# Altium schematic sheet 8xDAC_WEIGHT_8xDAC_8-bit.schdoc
size 420 x 297 mm; Symbol: Drawing-Symbol_A4; @Project Name: Inverted_MAML_6x6; @Page Count: 1; @Update Date: 2026-06-15; @Create Date: 2026-06-15; @Schematic Name: Schematic1; @Page No: 1; @Page Name: P1; Company: EasyEDA.com; Version: V1.0; Page Size: A4; Drawn: Olle Welin; Device: Drawing-Symbol_A4; @Create Time: 21:23:07; @Update Time: 21:23:07; Border: 1; Width: 1655; Height: 1170; Region Start: 1; X Region Count: 6; Y Region Count: 4; Blade Width: 10; Title Block Position: 3
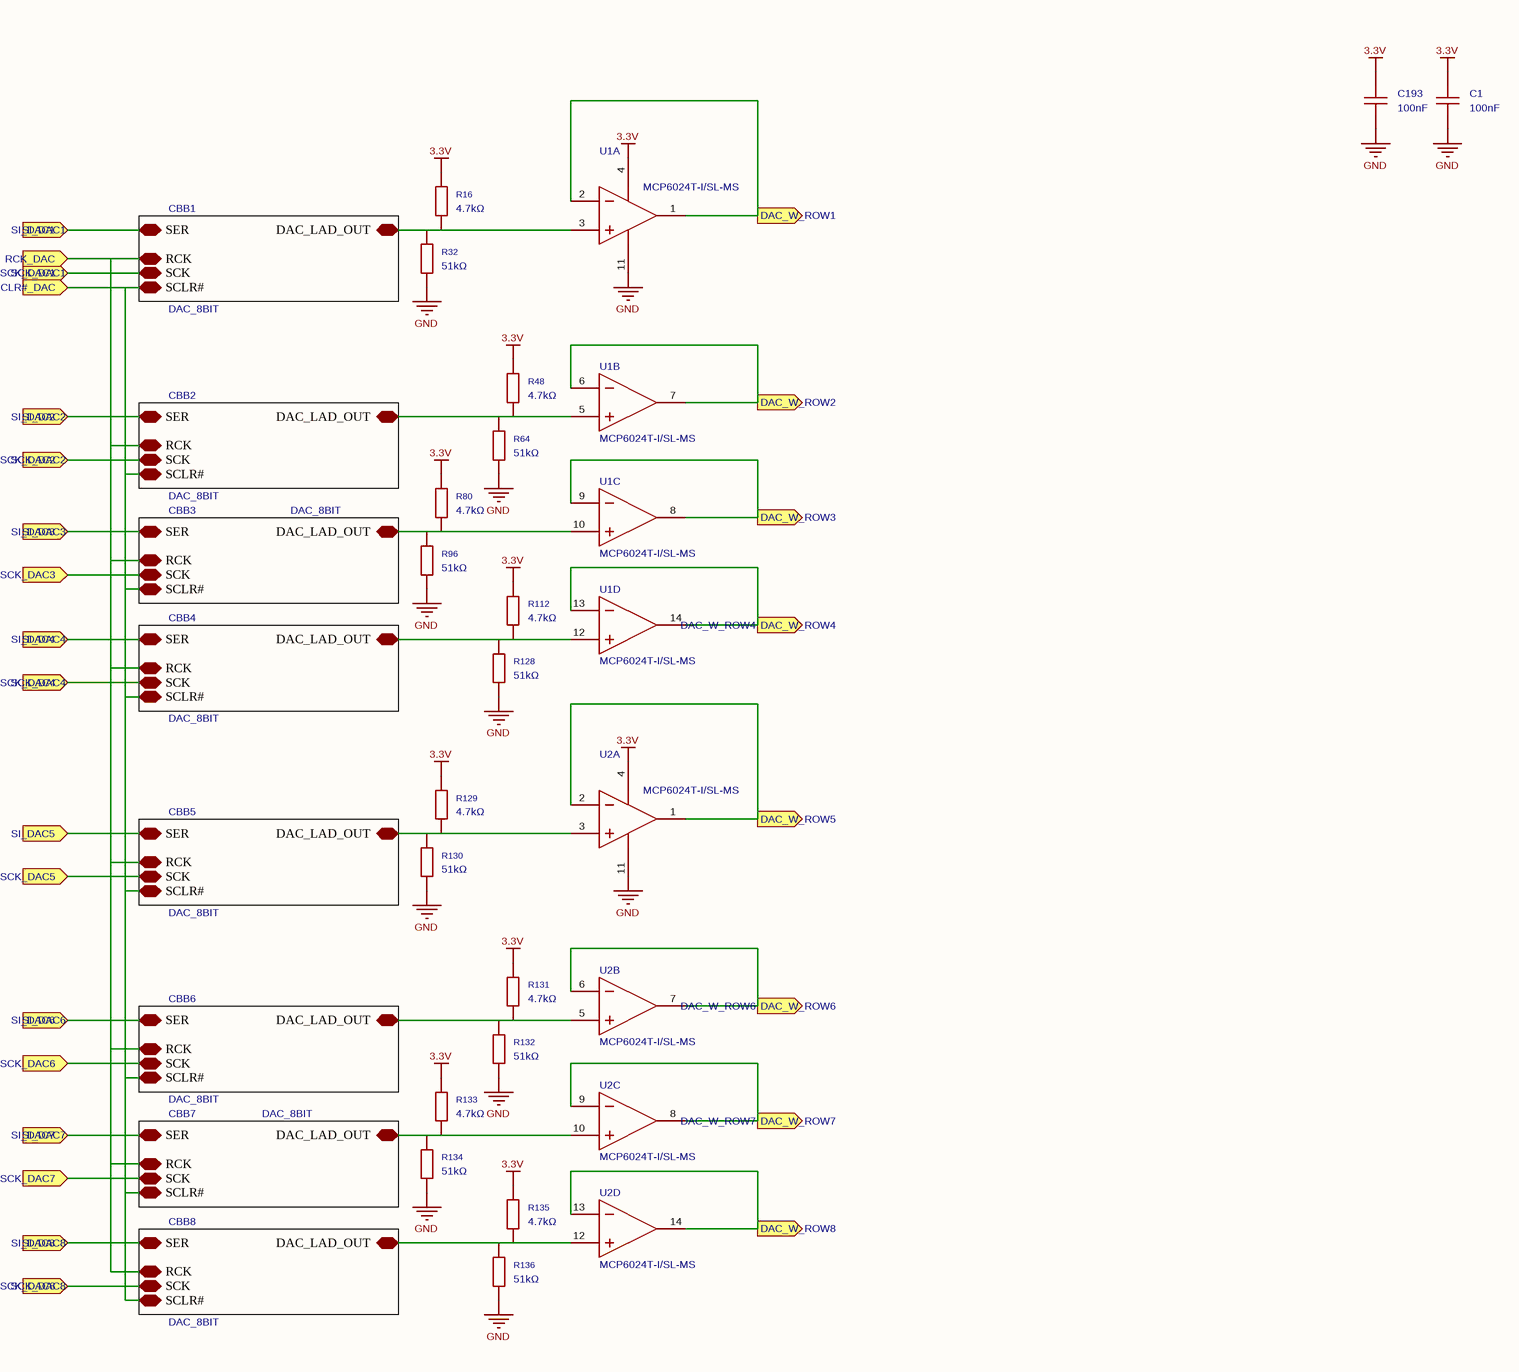
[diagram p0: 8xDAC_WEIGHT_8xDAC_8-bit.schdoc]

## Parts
C1  100nF  [C0402]
C193  100nF  [C0402]
R16  4.7kΩ  [R0402]
R32  51kΩ  [R0402]
R48  4.7kΩ  [R0402]
R64  51kΩ  [R0402]
R80  4.7kΩ  [R0402]
R96  51kΩ  [R0402]
R112  4.7kΩ  [R0402]
R128  51kΩ  [R0402]
R129  4.7kΩ  [R0402]
R130  51kΩ  [R0402]
R131  4.7kΩ  [R0402]
R132  51kΩ  [R0402]
R133  4.7kΩ  [R0402]
R134  51kΩ  [R0402]
R135  4.7kΩ  [R0402]
R136  51kΩ  [R0402]
U1  MCP6024T-I/SL-MS  [SOIC-14_L8.7-W3.9-P1.27-LS6.0-BL-1]  (parts A,B,C,D of 4)
U2  MCP6024T-I/SL-MS  [SOIC-14_L8.7-W3.9-P1.27-LS6.0-BL-1]  (parts A,B,C,D of 4)

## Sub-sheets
CBB1 = DAC_8B_R_2R.schdoc: SER, RCK, SCK, SCLR#, DAC_LAD_OUT  | Symbol: DAC_8BIT
CBB2 = DAC_8B_R_2R.schdoc: SER, RCK, SCK, SCLR#, DAC_LAD_OUT  | Symbol: DAC_8BIT
CBB3 = DAC_8B_R_2R.schdoc: SER, RCK, SCK, SCLR#, DAC_LAD_OUT  | Symbol: DAC_8BIT
CBB4 = DAC_8B_R_2R.schdoc: SER, RCK, SCK, SCLR#, DAC_LAD_OUT  | Symbol: DAC_8BIT
CBB5 = DAC_8B_R_2R.schdoc: SER, RCK, SCK, SCLR#, DAC_LAD_OUT  | Symbol: DAC_8BIT
CBB6 = DAC_8B_R_2R.schdoc: SER, RCK, SCK, SCLR#, DAC_LAD_OUT  | Symbol: DAC_8BIT
CBB7 = DAC_8B_R_2R.schdoc: SER, RCK, SCK, SCLR#, DAC_LAD_OUT  | Symbol: DAC_8BIT
CBB8 = DAC_8B_R_2R.schdoc: SER, RCK, SCK, SCLR#, DAC_LAD_OUT  | Symbol: DAC_8BIT

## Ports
DAC_W_ROW1 (out), DAC_W_ROW2 (out), DAC_W_ROW3 (out), DAC_W_ROW4 (out), DAC_W_ROW5 (out), DAC_W_ROW6 (out), DAC_W_ROW7 (out), DAC_W_ROW8 (out), RCK_DAC (in), SCK_DAC1 (in), SCK_DAC2 (in), SCK_DAC3 (in), SCK_DAC4 (in), SCK_DAC5 (in), SCK_DAC6 (in), SCK_DAC7 (in), SCK_DAC8 (in), SCLR#_DAC (in), SI_DAC1 (in), SI_DAC2 (in), SI_DAC3 (in), SI_DAC4 (in), SI_DAC5 (in), SI_DAC6 (in), SI_DAC7 (in), SI_DAC8 (in)

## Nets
3.3V: C1.2 C193.2 R16.2 R48.2 R80.2 R112.2 R129.2 R131.2 R133.2 R135.2 U1.4(V+) U2.4(V+)
GND: C1.1 C193.1 R32.1 R64.1 R96.1 R128.1 R130.1 R132.1 R134.1 R136.1 U1.11(V-) U2.11(V-)
DAC_W_ROW1: U1.1(OUT1) U1.2(IN1-) ; port DAC_W_ROW1
DAC_W_ROW2: U1.6(IN2-) U1.7(OUT2) ; port DAC_W_ROW2
DAC_W_ROW3: U1.8(OUT3) U1.9(IN3-) ; port DAC_W_ROW3
DAC_W_ROW4: U1.13(IN4-) U1.14(OUT4) ; port DAC_W_ROW4
DAC_W_ROW5: U2.1(OUT1) U2.2(IN1-) ; port DAC_W_ROW5
DAC_W_ROW6: U2.6(IN2-) U2.7(OUT2) ; port DAC_W_ROW6
DAC_W_ROW7: U2.8(OUT3) U2.9(IN3-) ; port DAC_W_ROW7
DAC_W_ROW8: U2.13(IN4-) U2.14(OUT4) ; port DAC_W_ROW8
RCK_DAC: port RCK_DAC, sheet CBB1/RCK, sheet CBB2/RCK, sheet CBB3/RCK, sheet CBB4/RCK, sheet CBB5/RCK, sheet CBB6/RCK, sheet CBB7/RCK, sheet CBB8/RCK
SCK_DAC1: port SCK_DAC1, sheet CBB1/SCK
SCK_DAC2: port SCK_DAC2, sheet CBB2/SCK
SCK_DAC3: port SCK_DAC3, sheet CBB3/SCK
SCK_DAC4: port SCK_DAC4, sheet CBB4/SCK
SCK_DAC5: port SCK_DAC5, sheet CBB5/SCK
SCK_DAC6: port SCK_DAC6, sheet CBB6/SCK
SCK_DAC7: port SCK_DAC7, sheet CBB7/SCK
SCK_DAC8: port SCK_DAC8, sheet CBB8/SCK
SCLR#_DAC: port SCLR#_DAC, sheet CBB1/SCLR#, sheet CBB2/SCLR#, sheet CBB3/SCLR#, sheet CBB4/SCLR#, sheet CBB5/SCLR#, sheet CBB6/SCLR#, sheet CBB7/SCLR#, sheet CBB8/SCLR#
SI_DAC1: port SI_DAC1, sheet CBB1/SER
SI_DAC2: port SI_DAC2, sheet CBB2/SER
SI_DAC3: port SI_DAC3, sheet CBB3/SER
SI_DAC4: port SI_DAC4, sheet CBB4/SER
SI_DAC5: port SI_DAC5, sheet CBB5/SER
SI_DAC6: port SI_DAC6, sheet CBB6/SER
SI_DAC7: port SI_DAC7, sheet CBB7/SER
SI_DAC8: port SI_DAC8, sheet CBB8/SER
NetR16_1: R16.1 R32.2 U1.3(IN1+) ; sheet CBB1/DAC_LAD_OUT
NetR48_1: R48.1 R64.2 U1.5(IN2+) ; sheet CBB2/DAC_LAD_OUT
NetR80_1: R80.1 R96.2 U1.10(IN3+) ; sheet CBB3/DAC_LAD_OUT
NetR112_1: R112.1 R128.2 U1.12(IN4+) ; sheet CBB4/DAC_LAD_OUT
NetR129_1: R129.1 R130.2 U2.3(IN1+) ; sheet CBB5/DAC_LAD_OUT
NetR131_1: R131.1 R132.2 U2.5(IN2+) ; sheet CBB6/DAC_LAD_OUT
NetR133_1: R133.1 R134.2 U2.10(IN3+) ; sheet CBB7/DAC_LAD_OUT
NetR135_1: R135.1 R136.2 U2.12(IN4+) ; sheet CBB8/DAC_LAD_OUT

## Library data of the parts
C1 C193 = CL05B104KO5NNNC: Capacitance:100nF Tolerance:±10% Tolerance:±10% Voltage Rating:16V Temperature Coefficient:X7R; Manufacturer: SAMSUNG(三星); 3D Model: b7d13df3e9464d7a99d0651d1a5b4d570819f05c4eef4c71ace90d822a990e87; 3D Model Transform: 39.37,19.685,0,0,0,0,0,0,0; Tolerance: ±10%; Voltage Rating: 16V; Temperature Coefficient: X7R; AddInBom: yes; ModelName: C0402_L1.0-W0.5-H0.5
R16 R48 R80 R112 R129 R131 R133 R135 = 0402WGF4701TCE: Type:Thick Film Resistor Resistance:4.7kΩ Tolerance:±1% Tolerance:±1% Power(Watts):62.5mW Voltage-Supply(Max):50V Temperature Coefficient:±100ppm/℃ Temperature Coefficient:±100ppm/℃ Operating Temperature:-55℃~+155℃ Operating Temperature:-55℃~+155℃; Manufacturer: UNI-ROYAL(厚声); AddInBom: yes; ModelId: efdecb7dae4442949d28eecaf748420f0819f05c4eef4c71ace90d822a990e87; ModelName: R0402_L1.0-W0.5-H0.4; ModelTransform: 39.37,19.685,0,0,0,0,0,0,0; Tolerance: ±1%; Power(Watts): 62.5mW; Voltage-Supply(Max): 50V
R32 R64 R96 R128 R130 R132 R134 R136 = 0402WGF5102TCE: Type:Thick Film Resistors Resistance:51kΩ Tolerance:±1% Tolerance:±1% Power(Watts): Overload Voltage (Max): Temperature Coefficient:±100ppm/℃ Temperature Coefficient:±100ppm/℃ Operating Temperature Range:-55℃~+155℃ Operating Temperature Range:-55℃~+155℃; Manufacturer: UNI-ROYAL(厚声); AddInBom: yes; ModelId: efdecb7dae4442949d28eecaf748420f0819f05c4eef4c71ace90d822a990e87; ModelName: R0402_L1.0-W0.5-H0.4; ModelTransform: 39.37,19.685,0,0,0,0,0,0,0; Tolerance: ±1%
U1 U2 = MCP6024T-I/SL-MS: Manufacturer: MSKSEMI(美森科); Relevance: []; AddInBom: yes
